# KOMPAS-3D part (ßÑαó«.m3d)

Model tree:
1. Эскиз:1
2. Операция выдавливания:1
     Расстояние 1 = 22.4; Расстояние 2 = 7.2
3. Эскиз:2
4. Операция выдавливания:2
     Расстояние 1 = 1; Расстояние 2 = 7.2
5. Эскиз:7
6. Вырезать элемент выдавливания:3
     Расстояние 1 = 3

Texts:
  stalker61
  Полипропилен  ГОСТ 26996-86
